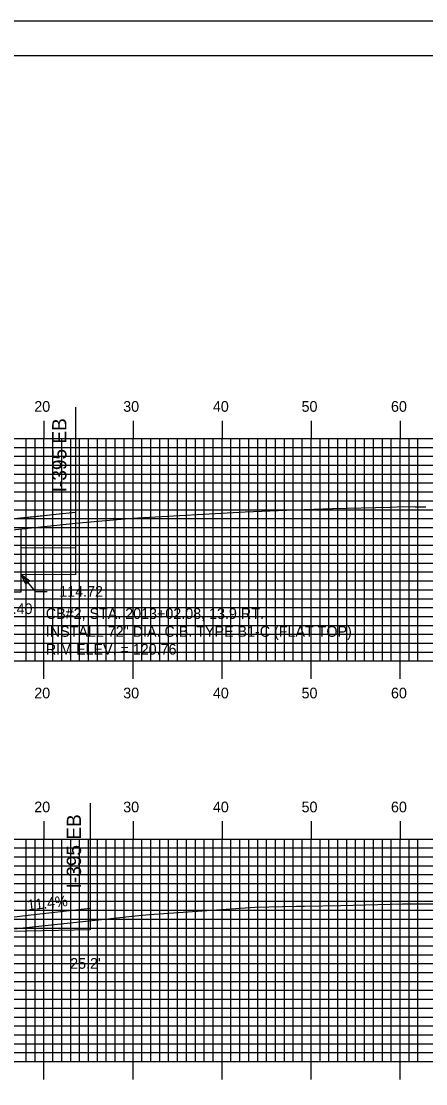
# Model space of a CAD drawing. Extents: x 853894 to 854237, y 366605 to 366825.
# Drawn here: x 854077 to 854122.4, y 366705.6 to 366824.9 of the extents above; entities that cross this region are included whole.
import ezdxf

# ---------------------------------------------------------------- set-up
doc = ezdxf.new("R2010")
doc.units = 0
for name, color, linetype in [('ANNOTATION', 7, 'Continuous'), ('BORDER', 7, 'Continuous'), ('D_Drainage_CB_TypeA1-B1', 7, 'Continuous'), ('D_Drainage_Culvert', 7, 'Continuous'), ('D_Roadway_Centerline', 7, 'Continuous'), ('D_Roadway_SubGrade', 7, 'Continuous'), ('D_Text_Standard', 7, 'Continuous'), ('H_V ANNOTATION', 7, 'Continuous'), ('M_Roadway_Centerline', 7, 'Continuous'), ('MAJOR', 7, 'Continuous'), ('MINOR', 7, 'Continuous'), ('PLOT BOUNDARY', 7, 'Continuous'), ('S_Roadway_Centerline', 7, 'Continuous')]:
    doc.layers.add(name, color=color, linetype=linetype)

msp = doc.modelspace()

# ---------------------------------------------------------------- linework, layer by layer
at = {"layer": 'BORDER'}
msp.add_lwpolyline([(853909.93, 366611.06), (854229.93, 366611.06), (854229.93, 366821.06), (853909.93, 366821.06)], close=True, dxfattribs=at)
at = {"layer": 'D_Drainage_CB_TypeA1-B1'}
msp.add_lwpolyline([(854073.98, 366760.83), (854076.98, 366760.83), (854076.98, 366767.83)], dxfattribs=at)
at = {"layer": 'D_Drainage_Culvert'}
for points in [[(854083.07, 366765.75), (854076.98, 366765.78)], [(854083.07, 366762.75), (854076.98, 366762.78)]]:
    msp.add_lwpolyline(points, dxfattribs=at)
at = {"layer": 'D_Roadway_Centerline'}
msp.add_line((854084.71, 366722.86), (854075.82, 366722.68), dxfattribs=at)
for points in [[(854063.68, 366769.8), (854073.98, 366768.83), (854083.07, 366769.78)], [(854073.98, 366768.83), (854074.61, 366768.9), (854074.73, 366768.91), (854077.51, 366769.2), (854079.27, 366769.38), (854080.54, 366769.52), (854083.07, 366769.78)], [(854074.69, 366724.14), (854077.41, 366724.45), (854084.71, 366725.28)]]:
    msp.add_lwpolyline(points, dxfattribs=at)
at = {"layer": 'D_Roadway_SubGrade'}
for p, q in [((854083.07, 366781.59), (854083.07, 366762.75)), ((854084.71, 366737.09), (854084.71, 366722.86))]:
    msp.add_line(p, q, dxfattribs=at)
at = {"layer": 'D_Text_Standard'}
msp.add_lwpolyline([(854076.98, 366762.78), (854077.94, 366762.05), (854077.49, 366761.69)], close=True, dxfattribs=at)
msp.add_lwpolyline([(854076.98, 366762.78), (854078.53, 366760.87), (854079.89, 366760.87)], dxfattribs=at)
at = {"layer": 'MAJOR'}
for p, q in [((854079.53, 366780.06), (854079.53, 366778.06)), ((854089.53, 366780.06), (854089.53, 366778.06)), ((854099.53, 366780.06), (854099.53, 366778.06)), ((854109.53, 366780.06), (854109.53, 366778.06)), ((854119.53, 366780.06), (854119.53, 366778.06)), ((853919.53, 366778.06), (854199.53, 366778.06)), ((853919.53, 366778.06), (854199.53, 366778.06)), ((854079.53, 366753.06), (854079.53, 366778.06)), ((854089.53, 366753.06), (854089.53, 366778.06)), ((854099.53, 366753.06), (854099.53, 366778.06)), ((854109.53, 366753.06), (854109.53, 366778.06)), ((854119.53, 366753.06), (854119.53, 366778.06)), ((853919.53, 366773.06), (854199.53, 366773.06)), ((853919.53, 366768.06), (854199.53, 366768.06)), ((853919.53, 366763.06), (854199.53, 366763.06)), ((853919.53, 366758.06), (854199.53, 366758.06)), ((853919.53, 366753.06), (854199.53, 366753.06)), ((853919.53, 366753.06), (854199.53, 366753.06)), ((854079.53, 366751.05), (854079.53, 366753.06)), ((854089.53, 366751.05), (854089.53, 366753.06)), ((854099.53, 366751.05), (854099.53, 366753.06)), ((854109.53, 366751.05), (854109.53, 366753.06)), ((854119.53, 366751.05), (854119.53, 366753.06)), ((854079.53, 366735.06), (854079.53, 366733.06)), ((854089.53, 366735.06), (854089.53, 366733.06)), ((854099.53, 366735.06), (854099.53, 366733.06)), ((854109.53, 366735.06), (854109.53, 366733.06)), ((854119.53, 366735.06), (854119.53, 366733.06)), ((853919.53, 366733.06), (854199.53, 366733.06)), ((853919.53, 366733.06), (854199.53, 366733.06)), ((854079.53, 366708.06), (854079.53, 366733.06)), ((854089.53, 366708.06), (854089.53, 366733.06)), ((854099.53, 366708.06), (854099.53, 366733.06)), ((854109.53, 366708.06), (854109.53, 366733.06)), ((854119.53, 366708.06), (854119.53, 366733.06)), ((853919.53, 366728.06), (854199.53, 366728.06)), ((853919.53, 366723.06), (854199.53, 366723.06)), ((853919.53, 366718.06), (854199.53, 366718.06)), ((853919.53, 366713.06), (854199.53, 366713.06)), ((853919.53, 366708.06), (854199.53, 366708.06)), ((853919.53, 366708.06), (854199.53, 366708.06)), ((854079.53, 366706.05), (854079.53, 366708.06)), ((854089.53, 366706.05), (854089.53, 366708.06)), ((854099.53, 366706.05), (854099.53, 366708.06)), ((854109.53, 366706.05), (854109.53, 366708.06)), ((854119.53, 366706.05), (854119.53, 366708.06))]:
    msp.add_line(p, q, dxfattribs=at)
at = {"layer": 'MINOR'}
for p, q in [((854077.53, 366753.06), (854077.53, 366778.06)), ((854078.53, 366753.06), (854078.53, 366778.06)), ((854080.53, 366753.06), (854080.53, 366778.06)), ((854081.53, 366753.06), (854081.53, 366778.06)), ((854082.53, 366753.06), (854082.53, 366778.06)), ((854083.53, 366753.06), (854083.53, 366778.06)), ((854084.53, 366753.06), (854084.53, 366778.06)), ((854085.53, 366753.06), (854085.53, 366778.06)), ((854086.53, 366753.06), (854086.53, 366778.06)), ((854087.53, 366753.06), (854087.53, 366778.06)), ((854088.53, 366753.06), (854088.53, 366778.06)), ((854090.53, 366753.06), (854090.53, 366778.06)), ((854091.53, 366753.06), (854091.53, 366778.06)), ((854092.53, 366753.06), (854092.53, 366778.06)), ((854093.53, 366753.06), (854093.53, 366778.06)), ((854094.53, 366753.06), (854094.53, 366778.06)), ((854095.53, 366753.06), (854095.53, 366778.06)), ((854096.53, 366753.06), (854096.53, 366778.06)), ((854097.53, 366753.06), (854097.53, 366778.06)), ((854098.53, 366753.06), (854098.53, 366778.06)), ((854100.53, 366753.06), (854100.53, 366778.06)), ((854101.53, 366753.06), (854101.53, 366778.06)), ((854102.53, 366753.06), (854102.53, 366778.06)), ((854103.53, 366753.06), (854103.53, 366778.06)), ((854104.53, 366753.06), (854104.53, 366778.06)), ((854105.53, 366753.06), (854105.53, 366778.06)), ((854106.53, 366753.06), (854106.53, 366778.06)), ((854107.53, 366753.06), (854107.53, 366778.06)), ((854108.53, 366753.06), (854108.53, 366778.06)), ((854110.53, 366753.06), (854110.53, 366778.06)), ((854111.53, 366753.06), (854111.53, 366778.06)), ((854112.53, 366753.06), (854112.53, 366778.06)), ((854113.53, 366753.06), (854113.53, 366778.06)), ((854114.53, 366753.06), (854114.53, 366778.06)), ((854115.53, 366753.06), (854115.53, 366778.06)), ((854116.53, 366753.06), (854116.53, 366778.06)), ((854117.53, 366753.06), (854117.53, 366778.06)), ((854118.53, 366753.06), (854118.53, 366778.06)), ((854120.53, 366753.06), (854120.53, 366778.06)), ((854121.53, 366753.06), (854121.53, 366778.06)), ((853919.53, 366777.06), (854199.53, 366777.06)), ((853919.53, 366776.06), (854199.53, 366776.06)), ((853919.53, 366775.06), (854199.53, 366775.06)), ((853919.53, 366774.06), (854199.53, 366774.06)), ((853919.53, 366772.06), (854199.53, 366772.06)), ((853919.53, 366771.06), (854199.53, 366771.06)), ((853919.53, 366770.06), (854199.53, 366770.06)), ((853919.53, 366769.06), (854199.53, 366769.06)), ((853919.53, 366767.06), (854199.53, 366767.06)), ((853919.53, 366766.06), (854199.53, 366766.06)), ((853919.53, 366765.06), (854199.53, 366765.06)), ((853919.53, 366764.06), (854199.53, 366764.06)), ((853919.53, 366762.06), (854199.53, 366762.06)), ((853919.53, 366761.06), (854199.53, 366761.06)), ((853919.53, 366760.06), (854199.53, 366760.06)), ((853919.53, 366759.06), (854199.53, 366759.06)), ((853919.53, 366757.06), (854199.53, 366757.06)), ((853919.53, 366756.06), (854199.53, 366756.06)), ((853919.53, 366755.06), (854199.53, 366755.06)), ((853919.53, 366754.06), (854199.53, 366754.06)), ((854077.53, 366708.06), (854077.53, 366733.06)), ((854078.53, 366708.06), (854078.53, 366733.06)), ((854080.53, 366708.06), (854080.53, 366733.06)), ((854081.53, 366708.06), (854081.53, 366733.06)), ((854082.53, 366708.06), (854082.53, 366733.06)), ((854083.53, 366708.06), (854083.53, 366733.06)), ((854084.53, 366708.06), (854084.53, 366733.06)), ((854085.53, 366708.06), (854085.53, 366733.06)), ((854086.53, 366708.06), (854086.53, 366733.06)), ((854087.53, 366708.06), (854087.53, 366733.06)), ((854088.53, 366708.06), (854088.53, 366733.06)), ((854090.53, 366708.06), (854090.53, 366733.06)), ((854091.53, 366708.06), (854091.53, 366733.06)), ((854092.53, 366708.06), (854092.53, 366733.06)), ((854093.53, 366708.06), (854093.53, 366733.06)), ((854094.53, 366708.06), (854094.53, 366733.06)), ((854095.53, 366708.06), (854095.53, 366733.06)), ((854096.53, 366708.06), (854096.53, 366733.06)), ((854097.53, 366708.06), (854097.53, 366733.06)), ((854098.53, 366708.06), (854098.53, 366733.06)), ((854100.53, 366708.06), (854100.53, 366733.06)), ((854101.53, 366708.06), (854101.53, 366733.06)), ((854102.53, 366708.06), (854102.53, 366733.06)), ((854103.53, 366708.06), (854103.53, 366733.06)), ((854104.53, 366708.06), (854104.53, 366733.06)), ((854105.53, 366708.06), (854105.53, 366733.06)), ((854106.53, 366708.06), (854106.53, 366733.06)), ((854107.53, 366708.06), (854107.53, 366733.06)), ((854108.53, 366708.06), (854108.53, 366733.06)), ((854110.53, 366708.06), (854110.53, 366733.06)), ((854111.53, 366708.06), (854111.53, 366733.06)), ((854112.53, 366708.06), (854112.53, 366733.06)), ((854113.53, 366708.06), (854113.53, 366733.06)), ((854114.53, 366708.06), (854114.53, 366733.06)), ((854115.53, 366708.06), (854115.53, 366733.06)), ((854116.53, 366708.06), (854116.53, 366733.06)), ((854117.53, 366708.06), (854117.53, 366733.06)), ((854118.53, 366708.06), (854118.53, 366733.06)), ((854120.53, 366708.06), (854120.53, 366733.06)), ((854121.53, 366708.06), (854121.53, 366733.06)), ((853919.53, 366732.06), (854199.53, 366732.06)), ((853919.53, 366731.06), (854199.53, 366731.06)), ((853919.53, 366730.06), (854199.53, 366730.06)), ((853919.53, 366729.06), (854199.53, 366729.06)), ((853919.53, 366727.06), (854199.53, 366727.06)), ((853919.53, 366726.06), (854199.53, 366726.06)), ((853919.53, 366725.06), (854199.53, 366725.06)), ((853919.53, 366724.06), (854199.53, 366724.06)), ((853919.53, 366722.06), (854199.53, 366722.06)), ((853919.53, 366721.06), (854199.53, 366721.06)), ((853919.53, 366720.06), (854199.53, 366720.06)), ((853919.53, 366719.06), (854199.53, 366719.06)), ((853919.53, 366717.06), (854199.53, 366717.06)), ((853919.53, 366716.06), (854199.53, 366716.06)), ((853919.53, 366715.06), (854199.53, 366715.06)), ((853919.53, 366714.06), (854199.53, 366714.06)), ((853919.53, 366712.06), (854199.53, 366712.06)), ((853919.53, 366711.06), (854199.53, 366711.06)), ((853919.53, 366710.06), (854199.53, 366710.06)), ((853919.53, 366709.06), (854199.53, 366709.06))]:
    msp.add_line(p, q, dxfattribs=at)
at = {"layer": 'PLOT BOUNDARY'}
msp.add_lwpolyline([(853893.74, 366604.94), (854233.74, 366604.94), (854233.74, 366824.94), (853893.74, 366824.94)], close=True, dxfattribs=at)
at = {"layer": 'S_Roadway_Centerline'}
for points in [[(854069.56, 366767.11), (854083.43, 366768.57), (854088.2, 366768.99), (854090.02, 366769.14), (854102.11, 366769.83), (854102.12, 366769.81), (854107.71, 366770.05), (854111.94, 366770.19), (854118.41, 366770.35), (854119.88, 366770.4), (854121.2, 366770.37), (854122.42, 366770.39)], [(854070.45, 366722.35), (854086.69, 366724.1), (854089.39, 366724.4), (854091.37, 366724.56), (854103.22, 366725.4), (854107.89, 366725.52), (854108.79, 366725.52), (854112.85, 366725.59), (854119.8, 366725.77), (854120.39, 366725.78), (854120.89, 366725.77), (854125.93, 366725.77)]]:
    msp.add_lwpolyline(points, dxfattribs=at)

# ---------------------------------------------------------------- texts
at = {"layer": 'ANNOTATION'}
for s, height, rotation, p in [('I-395 EB', 1.6, 90, (854082.05, 366772.01)), ('I-395 EB', 1.6, 90, (854083.69, 366727.51)), ('11.4%', 1.2, 6.5024, (854077.72, 366725.02))]:
    msp.add_text(s, height=height, rotation=rotation, dxfattribs=at).set_placement(p)
for s, p in [('CB#2, STA. 2013+02.08, 13.9 RT.', (854079.74, 366757.79)), ('INSTALL 72" DIA. C.B. TYPE B1-C (FLAT TOP)', (854079.74, 366755.78)), ('RIM ELEV. = 120.76', (854079.74, 366753.78))]:
    msp.add_text(s, height=1.2, dxfattribs=at).set_placement(p)
at = {"layer": 'D_Text_Standard'}
for s, p in [('114.72', (854081.25, 366760.27)), ('117.40', (854073.33, 366758.33)), ("25.2'", (854082.47, 366718.48))]:
    msp.add_text(s, height=1.2, dxfattribs=at).set_placement(p)
at = {"layer": 'H_V ANNOTATION'}
for s, p in [('20', (854078.44, 366781.06)), ('30', (854088.43, 366781.06)), ('40', (854098.5, 366781.06)), ('50', (854108.46, 366781.06)), ('60', (854118.5, 366781.06)), ('20', (854078.44, 366748.86)), ('30', (854088.43, 366748.86)), ('40', (854098.5, 366748.86)), ('50', (854108.46, 366748.86)), ('60', (854118.5, 366748.86)), ('20', (854078.44, 366736.06)), ('30', (854088.43, 366736.06)), ('40', (854098.5, 366736.06)), ('50', (854108.46, 366736.06)), ('60', (854118.5, 366736.06))]:
    msp.add_text(s, height=1.2, dxfattribs=at).set_placement(p)
at = {"layer": 'M_Roadway_Centerline'}
for s, p in [('C', (854120.39, 366725.78)), ('L', (854120.39, 366725.77))]:
    msp.add_text(s, height=0.0146, dxfattribs=at).set_placement(p)

doc.saveas('drawing.dxf')
